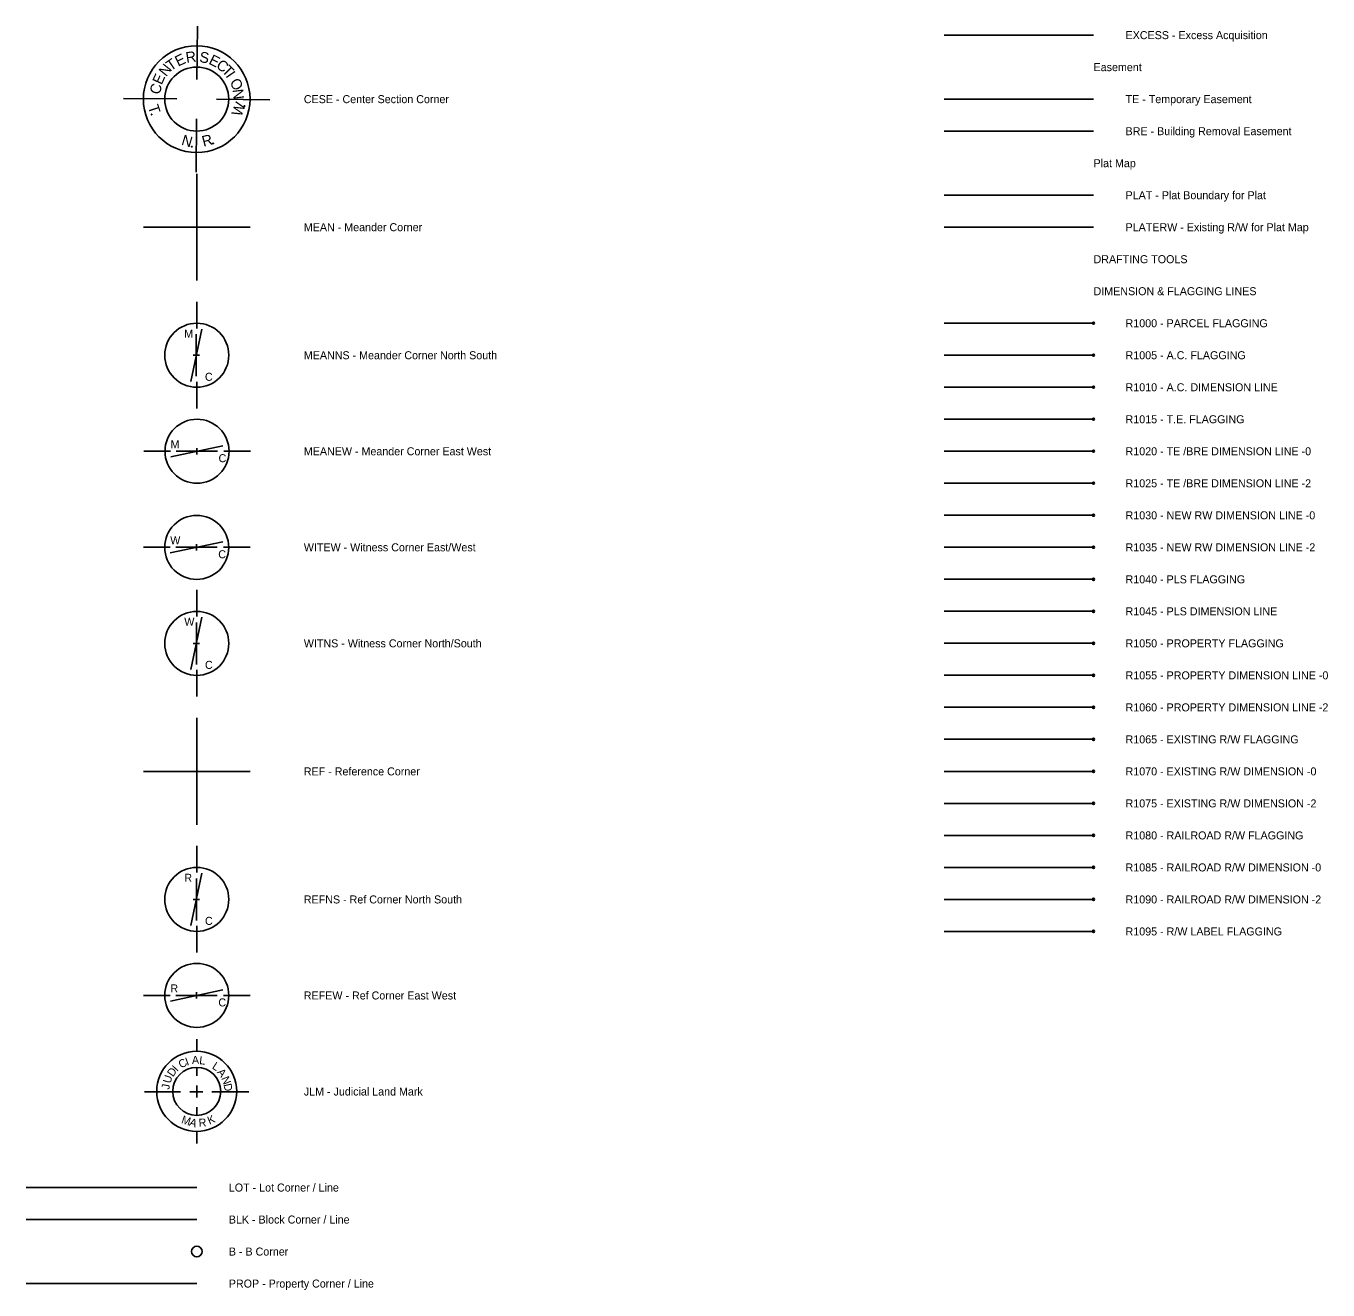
# Model space of a CAD drawing. Extents: x 2147712 to 2176316, y 2125036 to 2131746.
# Drawn here: x 2167426 to 2168646, y 2127705 to 2128889 of the extents above; entities that cross this region are included whole.
import ezdxf

# ---------------------------------------------------------------- set-up
doc = ezdxf.new("R2010")
doc.units = 0
for name, color, linetype in [('ACC CTRL DIM', 7, 'Continuous'), ('ACQ CHN RW', 7, 'Continuous'), ('B PT', 7, 'Continuous'), ('Default', 7, 'Continuous'), ('ESMT DIM', 7, 'Continuous'), ('ESMT FLAG', 7, 'Continuous'), ('ESMT TEMP', 7, 'Continuous'), ('GPK DEF', 7, 'Continuous'), ('PAR FLAG', 7, 'Continuous'), ('PLAT BDRY', 7, 'Continuous'), ('PLS INP', 7, 'Continuous'), ('PLS MLS INP DIM', 7, 'Continuous'), ('PROP INP', 7, 'Continuous'), ('RW INP', 7, 'Continuous'), ('RW INP DIM', 7, 'Continuous'), ('RW INP FLAG', 7, 'Continuous'), ('RW TXT DIM', 7, 'Continuous'), ('SUBD INP', 7, 'Continuous')]:
    doc.layers.add(name, color=color, linetype=linetype)

msp = doc.modelspace()

# ---------------------------------------------------------------- linework, layer by layer
at = {"layer": 'ACC CTRL DIM'}
msp.add_line((2168426.1, 2128550.6), (2168286.1, 2128550.6), dxfattribs=at)
msp.add_circle((2168426.1, 2128550.6), 1, dxfattribs=at)
at = {"layer": 'ACQ CHN RW'}
msp.add_line((2168426.1, 2128880.6), (2168286.1, 2128880.6), dxfattribs=at)
at = {"layer": 'B PT'}
msp.add_circle((2167585.7, 2127740.6), 5, dxfattribs=at)
at = {"layer": 'ESMT DIM'}
for p, q in [((2168426.1, 2128490.6), (2168286.1, 2128490.6)), ((2168426.1, 2128460.6), (2168286.1, 2128460.6))]:
    msp.add_line(p, q, dxfattribs=at)
for centre in [(2168426.1, 2128490.6), (2168426.1, 2128460.6)]:
    msp.add_circle(centre, 1, dxfattribs=at)
at = {"layer": 'ESMT FLAG'}
msp.add_line((2168426.1, 2128520.6), (2168286.1, 2128520.6), dxfattribs=at)
msp.add_circle((2168426.1, 2128520.6), 1, dxfattribs=at)
at = {"layer": 'ESMT TEMP'}
for p, q in [((2168426.1, 2128820.6), (2168286.1, 2128820.6)), ((2168426.1, 2128790.6), (2168286.1, 2128790.6))]:
    msp.add_line(p, q, dxfattribs=at)
at = {"layer": 'GPK DEF'}
for p, q in [((2167585.7, 2128750.6), (2167585.7, 2128650.6)), ((2167635.7, 2128700.6), (2167535.7, 2128700.6)), ((2167585.7, 2128240.6), (2167585.7, 2128140.6)), ((2167635.7, 2128190.6), (2167535.7, 2128190.6))]:
    msp.add_line(p, q, dxfattribs=at)
at = {"layer": 'PAR FLAG'}
for p, q in [((2168426.1, 2128610.6), (2168286.1, 2128610.6)), ((2168426.1, 2128580.6), (2168286.1, 2128580.6)), ((2168426.1, 2128310.6), (2168286.1, 2128310.6))]:
    msp.add_line(p, q, dxfattribs=at)
for centre in [(2168426.1, 2128610.6), (2168426.1, 2128580.6), (2168426.1, 2128310.6)]:
    msp.add_circle(centre, 1, dxfattribs=at)
at = {"layer": 'PLAT BDRY'}
msp.add_line((2168426.1, 2128730.6), (2168286.1, 2128730.6), dxfattribs=at)
at = {"layer": 'PLS INP'}
for p, q in [((2167585.8, 2128839.1), (2167586.2, 2128889.1)), ((2167517.1, 2128821.2), (2167567.1, 2128820.8)), ((2167604.1, 2128820.4), (2167654.1, 2128820)), ((2167585, 2128752.1), (2167585.4, 2128802.1)), ((2167585.6, 2128605.6), (2167585.6, 2128630.6)), ((2167580, 2128555.9), (2167590.4, 2128605.1)), ((2167585.2, 2128600.2), (2167585.2, 2128560.8)), ((2167585.2, 2128580.5), (2167582.2, 2128580.5)), ((2167585.2, 2128580.7), (2167585.2, 2128580.7)), ((2167585.2, 2128580.5), (2167588.2, 2128580.5)), ((2167585.6, 2128555.6), (2167585.6, 2128530.6)), ((2167561.4, 2128485.5), (2167610, 2128495.7)), ((2167585.7, 2128490.6), (2167585.7, 2128493.6)), ((2167535.9, 2128490.6), (2167560.9, 2128490.6)), ((2167566.4, 2128490.6), (2167605, 2128490.6)), ((2167585.5, 2128490.6), (2167585.5, 2128490.6)), ((2167585.7, 2128487.6), (2167585.7, 2128490.6)), ((2167610.9, 2128490.6), (2167635.9, 2128490.6)), ((2167535.6, 2128400.6), (2167560.6, 2128400.6)), ((2167560.7, 2128395.4), (2167610.1, 2128405.8)), ((2167566.1, 2128400.6), (2167604.7, 2128400.6)), ((2167585.2, 2128400.6), (2167585.2, 2128400.6)), ((2167585.4, 2128400.6), (2167585.4, 2128403.6)), ((2167585.4, 2128400.6), (2167585.4, 2128397.6)), ((2167610.6, 2128400.6), (2167635.6, 2128400.6)), ((2168426.1, 2128370.6), (2168286.1, 2128370.6)), ((2167585.7, 2128335.6), (2167585.7, 2128360.6)), ((2167580.1, 2128285.9), (2167590.5, 2128335.1)), ((2167585.3, 2128330.2), (2167585.3, 2128290.8)), ((2167585.3, 2128310.5), (2167582.3, 2128310.5)), ((2167585.3, 2128310.7), (2167585.3, 2128310.7)), ((2167585.3, 2128310.5), (2167588.3, 2128310.5)), ((2167585.7, 2128285.6), (2167585.7, 2128260.6)), ((2167585.7, 2128095.7), (2167585.7, 2128120.7)), ((2167580.1, 2128046), (2167590.5, 2128095.2)), ((2167585.3, 2128090.3), (2167585.3, 2128050.9)), ((2167585.3, 2128070.6), (2167582.3, 2128070.6)), ((2167585.3, 2128070.7), (2167585.3, 2128070.7)), ((2167585.3, 2128070.6), (2167588.3, 2128070.6)), ((2167585.7, 2128045.7), (2167585.7, 2128020.7)), ((2167535.7, 2127980.6), (2167560.7, 2127980.6)), ((2167560.9, 2127975.3), (2167610.1, 2127985.9)), ((2167566.2, 2127980.6), (2167604.8, 2127980.6)), ((2167585.3, 2127980.6), (2167585.3, 2127980.6)), ((2167585.5, 2127980.6), (2167585.5, 2127983.6)), ((2167585.5, 2127977.6), (2167585.5, 2127980.6)), ((2167610.7, 2127980.6), (2167635.7, 2127980.6)), ((2167585.7, 2127928.2), (2167585.7, 2127939.7)), ((2167585.7, 2127905.1), (2167585.7, 2127913.2)), ((2167585.7, 2127884.8), (2167585.7, 2127896.3)), ((2167570.3, 2127890.4), (2167536.7, 2127890.4)), ((2167591.3, 2127890.4), (2167579.2, 2127890.4)), ((2167585.7, 2127890.7), (2167585.7, 2127890.4)), ((2167599.8, 2127890.4), (2167634.6, 2127890.4)), ((2167585.7, 2127875.9), (2167585.7, 2127868.2)), ((2167585.7, 2127853.2), (2167585.7, 2127841.7))]:
    msp.add_line(p, q, dxfattribs=at)
for centre, radius in [((2167585.6, 2128820.6), 50), ((2167585.6, 2128820.6), 30), ((2167630.4, 2128814.1), 0.3), ((2167543.3, 2128806.2), 0.3), ((2167581, 2128776), 0.3), ((2167601, 2128779.1), 0.3), ((2167585.7, 2128580.6), 30), ((2167585.9, 2128490.6), 30), ((2167585.6, 2128400.5), 30), ((2168426.1, 2128370.6), 1), ((2167585.7, 2128310.5), 30), ((2167585.7, 2128070.6), 30), ((2167585.7, 2127980.6), 30), ((2167585.6, 2127890.7), 37.5), ((2167585.6, 2127890.7), 22.5)]:
    msp.add_circle(centre, radius, dxfattribs=at)
at = {"layer": 'PLS MLS INP DIM'}
msp.add_line((2168426.1, 2128340.6), (2168286.1, 2128340.6), dxfattribs=at)
msp.add_circle((2168426.1, 2128340.6), 1, dxfattribs=at)
at = {"layer": 'PROP INP'}
for p, q in [((2168426.1, 2128280.6), (2168286.1, 2128280.6)), ((2168426.1, 2128250.6), (2168286.1, 2128250.6)), ((2167585.7, 2127710.6), (2167425.7, 2127710.6))]:
    msp.add_line(p, q, dxfattribs=at)
for centre in [(2168426.1, 2128280.6), (2168426.1, 2128250.6)]:
    msp.add_circle(centre, 1, dxfattribs=at)
at = {"layer": 'RW INP'}
msp.add_line((2168426.1, 2128700.6), (2168286.1, 2128700.6), dxfattribs=at)
at = {"layer": 'RW INP DIM'}
for p, q in [((2168426.1, 2128190.6), (2168286.1, 2128190.6)), ((2168426.1, 2128160.6), (2168286.1, 2128160.6)), ((2168426.1, 2128100.6), (2168286.1, 2128100.6)), ((2168426.1, 2128070.6), (2168286.1, 2128070.6))]:
    msp.add_line(p, q, dxfattribs=at)
for centre in [(2168426.1, 2128190.6), (2168426.1, 2128160.6), (2168426.1, 2128100.6), (2168426.1, 2128070.6)]:
    msp.add_circle(centre, 1, dxfattribs=at)
at = {"layer": 'RW INP FLAG'}
for p, q in [((2168426.1, 2128220.6), (2168286.1, 2128220.6)), ((2168426.1, 2128130.6), (2168286.1, 2128130.6)), ((2168426.1, 2128040.6), (2168286.1, 2128040.6))]:
    msp.add_line(p, q, dxfattribs=at)
for centre in [(2168426.1, 2128220.6), (2168426.1, 2128130.6), (2168426.1, 2128040.6)]:
    msp.add_circle(centre, 1, dxfattribs=at)
at = {"layer": 'RW TXT DIM'}
for p, q in [((2168426.1, 2128430.6), (2168286.1, 2128430.6)), ((2168426.1, 2128400.6), (2168286.1, 2128400.6))]:
    msp.add_line(p, q, dxfattribs=at)
for centre in [(2168426.1, 2128430.6), (2168426.1, 2128400.6)]:
    msp.add_circle(centre, 1, dxfattribs=at)
at = {"layer": 'SUBD INP'}
for p, q in [((2167585.7, 2127800.6), (2167425.7, 2127800.6)), ((2167585.7, 2127770.6), (2167425.7, 2127770.6))]:
    msp.add_line(p, q, dxfattribs=at)

# ---------------------------------------------------------------- texts
at = {"layer": 'Default'}
for s, p in [('EXCESS - Excess Acquisition', (2168456.1, 2128876.8)), ('Easement', (2168426.1, 2128846.8)), ('CESE - Center Section Corner', (2167686, 2128816.8)), ('TE - Temporary Easement', (2168456.1, 2128816.8)), ('BRE - Building Removal Easement', (2168456.1, 2128786.8)), ('Plat Map', (2168426.1, 2128756.8)), ('PLAT - Plat Boundary for Plat', (2168456.1, 2128726.8)), ('MEAN - Meander Corner', (2167686, 2128696.8)), ('PLATERW - Existing R/W for Plat Map', (2168456.1, 2128696.8)), ('DRAFTING TOOLS', (2168426.1, 2128666.8)), ('DIMENSION & FLAGGING LINES', (2168426.1, 2128636.8)), ('R1000 - PARCEL FLAGGING', (2168456.1, 2128606.8)), ('MEANNS - Meander Corner North South', (2167686, 2128576.8)), ('R1005 - A.C. FLAGGING', (2168456.1, 2128576.8)), ('R1010 - A.C. DIMENSION LINE', (2168456.1, 2128546.8)), ('R1015 - T.E. FLAGGING', (2168456.1, 2128516.8)), ('MEANEW - Meander Corner East West', (2167686, 2128486.8)), ('R1020 - TE /BRE DIMENSION LINE -0', (2168456.1, 2128486.8)), ('R1025 - TE /BRE DIMENSION LINE -2', (2168456.1, 2128456.8)), ('R1030 - NEW RW DIMENSION LINE -0', (2168456.1, 2128426.8)), ('WITEW - Witness Corner East/West', (2167686, 2128396.8)), ('R1035 - NEW RW DIMENSION LINE -2', (2168456.1, 2128396.8)), ('R1040 - PLS FLAGGING', (2168456.1, 2128366.8)), ('R1045 - PLS DIMENSION LINE', (2168456.1, 2128336.8)), ('WITNS - Witness Corner North/South', (2167686, 2128306.8)), ('R1050 - PROPERTY FLAGGING', (2168456.1, 2128306.8)), ('R1055 - PROPERTY DIMENSION LINE -0', (2168456.1, 2128276.8)), ('R1060 - PROPERTY DIMENSION LINE -2', (2168456.1, 2128246.8)), ('R1065 - EXISTING R/W FLAGGING', (2168456.1, 2128216.8)), ('REF - Reference Corner', (2167686, 2128186.8)), ('R1070 - EXISTING R/W DIMENSION -0', (2168456.1, 2128186.8)), ('R1075 - EXISTING R/W DIMENSION -2', (2168456.1, 2128156.8)), ('R1080 - RAILROAD R/W FLAGGING', (2168456.1, 2128126.8)), ('R1085 - RAILROAD R/W DIMENSION -0', (2168456.1, 2128096.8)), ('REFNS - Ref Corner North South', (2167686, 2128066.8)), ('R1090 - RAILROAD R/W DIMENSION -2', (2168456.1, 2128066.8)), ('R1095 - R/W LABEL FLAGGING', (2168456.1, 2128036.8)), ('REFEW - Ref Corner East West', (2167686, 2127976.8)), ('JLM - Judicial Land Mark', (2167686, 2127886.8)), ('LOT - Lot Corner / Line', (2167615.7, 2127796.8)), ('BLK - Block Corner / Line', (2167615.7, 2127766.8)), ('B - B Corner', (2167615.7, 2127736.8)), ('PROP - Property Corner / Line', (2167615.7, 2127706.8))]:
    msp.add_text(s, height=7.5, dxfattribs=at).set_placement(p)
at = {"layer": 'PLS INP'}
for s, height, rotation, p in [('T', 10, 34.3025, (2167561.3, 2128846.5)), ('E', 10, 25.6946, (2167568.2, 2128850.9)), ('R', 10, 8.6953, (2167576.1, 2128854.5)), ('S', 10, 351.8558, (2167587.7, 2128855.3)), ('E', 10, 333.3184, (2167596.1, 2128854)), ('N', 10, 51.6315, (2167557, 2128841)), ('C', 10, 326.9714, (2167603.1, 2128850.2)), ('T', 10, 314.5065, (2167608.6, 2128846.6)), ('I', 10, 304.4985, (2167612.3, 2128842.4)), ('C', 10, 75.2692, (2167550.9, 2128824.3)), ('E', 10, 65.544, (2167552.7, 2128833.4)), ('O', 10, 302.9719, (2167616, 2128836.1)), ('N', 10, 277.2716, (2167619.1, 2128829.4)), ('T', 10, 288.1938, (2167539.8, 2128813.6)), ('W', 10, 69.5065, (2167627.3, 2128803.5)), ('N', 10, 343.2124, (2167570.6, 2128778)), ('R', 10, 14.7616, (2167592, 2128775.9)), ('C', 7.5, 28.7641, (2167571, 2127912)), ('I', 7.5, 19.9667, (2167576.5, 2127914.7)), ('A', 7.5, 2.372, (2167581.2, 2127916.3)), ('L', 7.5, 353.5747, (2167587.7, 2127916.3)), ('D', 7.5, 55.1561, (2167563.4, 2127903.8)), ('I', 7.5, 46.3587, (2167567.3, 2127908.7)), ('L', 7.5, 327.1827, (2167599.4, 2127912.5)), ('A', 7.5, 309.588, (2167604.3, 2127908.4)), ('J', 7.5, 81.5481, (2167559.9, 2127892.1)), ('U', 7.5, 72.7507, (2167560.9, 2127897.6)), ('N', 7.5, 291.9933, (2167608.5, 2127903)), ('D', 7.5, 283.196, (2167610.6, 2127897.1)), ('M', 7.5, 342.1117, (2167570.7, 2127861.1)), ('A', 7.5, 341.8523, (2167578.1, 2127858.8)), ('R', 7.5, 4.0842, (2167587.7, 2127857.4)), ('K', 7.5, 22.4608, (2167597.5, 2127859.5))]:
    msp.add_text(s, height=height, rotation=rotation, dxfattribs=at).set_placement(p)
for s, p in [('M', (2167573.9, 2128597)), ('C', (2167593.3, 2128556.6)), ('M', (2167561.1, 2128493.4)), ('C', (2167606.1, 2128480.3)), ('W', (2167560.8, 2128403.4)), ('C', (2167605.8, 2128390.3)), ('W', (2167574, 2128327)), ('C', (2167593.4, 2128286.6)), ('R', (2167574, 2128087.1)), ('C', (2167593.4, 2128046.7)), ('R', (2167560.9, 2127983.4)), ('C', (2167605.9, 2127970.3))]:
    msp.add_text(s, height=7.5, dxfattribs=at).set_placement(p)

doc.saveas('drawing.dxf')
